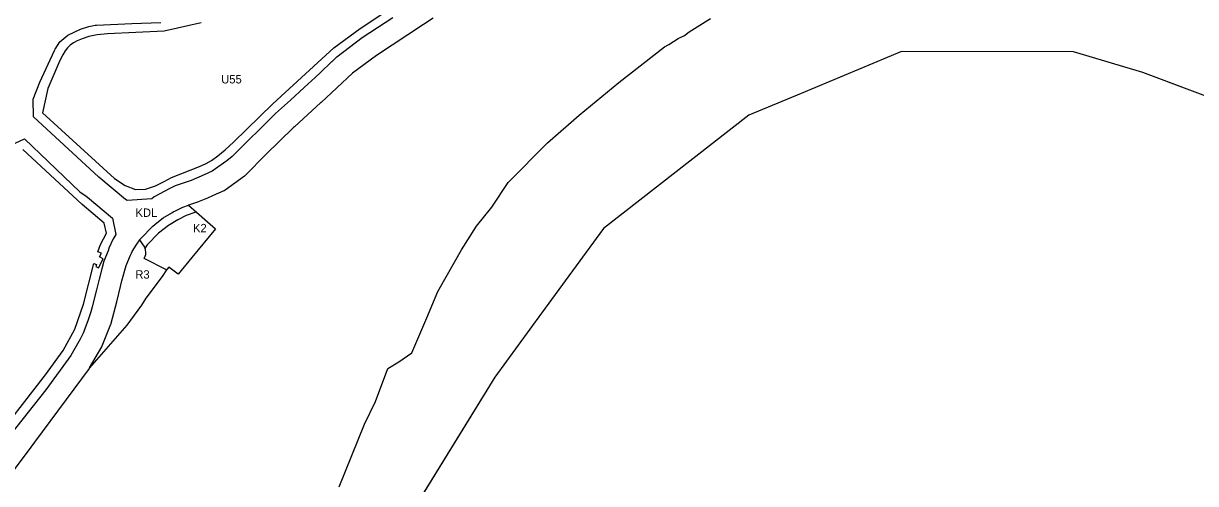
# Model space of a CAD drawing. Extents: x 7428103 to 7431580, y 5545880 to 5549002.
# Drawn here: x 7429439 to 7430217, y 5546339 to 5546645 of the extents above; entities that cross this region are included whole.
import ezdxf

# ---------------------------------------------------------------- set-up
doc = ezdxf.new("R2010")
doc.units = 0
for name, color, linetype in [('CZ_L_granica obszaru objętego planem', 7, 'Continuous'), ('CZ_L_linie rozgraniczające tereny o różnym przeznaczeniu oraz różnych warunkach ich zabudowy i zagospodarowania', 7, 'Continuous'), ('CZ_L_maksymalne nieprzekraczalne linie zabudowy', 7, 'Continuous'), ('CZ_L_opisy_linie rozgraniczające tereny o różnym przeznaczeniu oraz różnych warunkach ich zabudowy i zagospodarowania', 7, 'Continuous')]:
    doc.layers.add(name, color=color, linetype=linetype)

msp = doc.modelspace()

# ---------------------------------------------------------------- linework, layer by layer
at = {"layer": 'CZ_L_granica obszaru objętego planem'}
for p, q in [((7430022.09, 5546625.96), (7429955.41, 5546598.22)), ((7430136.35, 5546625.79), (7430022.09, 5546625.96)), ((7430182.29, 5546612.02), (7430136.35, 5546625.79)), ((7430241.16, 5546589.97), (7430182.29, 5546612.02)), ((7429955.41, 5546598.22), (7429920.79, 5546583.82)), ((7429920.79, 5546583.82), (7429824.25, 5546508.52)), ((7429824.25, 5546508.52), (7429783.16, 5546452.3)), ((7429783.16, 5546452.3), (7429752.12, 5546409.83)), ((7429752.12, 5546409.83), (7429678.23, 5546289.98))]:
    msp.add_line(p, q, dxfattribs=at)
at = {"layer": 'CZ_L_linie rozgraniczające tereny o różnym przeznaczeniu oraz różnych warunkach ich zabudowy i zagospodarowania'}
for p, q in [((7429684.51, 5546648.33), (7429664.19, 5546634.98)), ((7429711.15, 5546647.99), (7429704.83, 5546643.84)), ((7429881.09, 5546639.13), (7429895.22, 5546647.94)), ((7429468.75, 5546636.86), (7429477.04, 5546640.85)), ((7429477.04, 5546640.85), (7429482.63, 5546642.66)), ((7429482.63, 5546642.66), (7429482.65, 5546642.67)), ((7429482.65, 5546642.67), (7429484.85, 5546643.09)), ((7429484.85, 5546643.09), (7429486.9, 5546643.49)), ((7429486.9, 5546643.49), (7429487.78, 5546643.52)), ((7429487.78, 5546643.52), (7429511.19, 5546644.47)), ((7429511.19, 5546644.47), (7429530.49, 5546645.25)), ((7429704.83, 5546643.84), (7429673.62, 5546623.37)), ((7429878.13, 5546636.65), (7429881.09, 5546639.13)), ((7429460.33, 5546627.49), (7429463.44, 5546632.37)), ((7429463.44, 5546632.37), (7429468.75, 5546636.86)), ((7429664.19, 5546634.98), (7429647.18, 5546622.19)), ((7429864.76, 5546629.14), (7429867.67, 5546630.54)), ((7429867.67, 5546630.54), (7429873.82, 5546634.59)), ((7429873.82, 5546634.59), (7429878.13, 5546636.65)), ((7429450.16, 5546605.74), (7429459.9, 5546626.57)), ((7429459.9, 5546626.57), (7429460.33, 5546627.49)), ((7429673.62, 5546623.37), (7429657.76, 5546611.58)), ((7429834.39, 5546605.52), (7429864.76, 5546629.14)), ((7429643.82, 5546619.05), (7429636.42, 5546612.14)), ((7429643.88, 5546619.11), (7429643.82, 5546619.11)), ((7429643.82, 5546619.11), (7429643.82, 5546619.05)), ((7429647.15, 5546622.16), (7429643.88, 5546619.11)), ((7429647.18, 5546622.19), (7429647.15, 5546622.16)), ((7429632.88, 5546608.84), (7429625.65, 5546602.09)), ((7429636.37, 5546612.1), (7429632.88, 5546608.84)), ((7429636.42, 5546612.14), (7429636.37, 5546612.1)), ((7429657.76, 5546611.58), (7429636.78, 5546592.11)), ((7429445.68, 5546594.41), (7429450.16, 5546605.74)), ((7429625.65, 5546602.09), (7429616.47, 5546593.62)), ((7429808.18, 5546583.73), (7429834.39, 5546605.52)), ((7429446.02, 5546582.59), (7429445.68, 5546594.41)), ((7429616.47, 5546593.62), (7429606.57, 5546584.87)), ((7429636.75, 5546592.08), (7429619.18, 5546576.05)), ((7429636.77, 5546592.1), (7429636.75, 5546592.08)), ((7429636.78, 5546592.11), (7429636.77, 5546592.1)), ((7429606.57, 5546584.87), (7429601.7, 5546580.09)), ((7429787.2, 5546565.42), (7429808.18, 5546583.73)), ((7429489.21, 5546542.65), (7429446.02, 5546582.59)), ((7429601.7, 5546580.09), (7429582.94, 5546561.45)), ((7429619.18, 5546576.05), (7429618.62, 5546575.5)), ((7429618.62, 5546575.5), (7429600.18, 5546557.64)), ((7429433.85, 5546565.21), (7429440.07, 5546568.03)), ((7429440.07, 5546568.03), (7429476.81, 5546532.95)), ((7429582.94, 5546561.45), (7429577.71, 5546556.31)), ((7429761.07, 5546538.97), (7429787.2, 5546565.42)), ((7429574.26, 5546553.36), (7429564.63, 5546546.51)), ((7429577.71, 5546556.31), (7429574.26, 5546553.36)), ((7429600.18, 5546557.64), (7429586.75, 5546543.9)), ((7429564.63, 5546546.51), (7429559.22, 5546544.19)), ((7429507.09, 5546527.74), (7429489.21, 5546542.65)), ((7429550.69, 5546540.46), (7429540.07, 5546536.8)), ((7429559.22, 5546544.19), (7429550.69, 5546540.46)), ((7429586.1, 5546543.34), (7429573.24, 5546534.08)), ((7429586.66, 5546543.83), (7429586.1, 5546543.34)), ((7429586.75, 5546543.9), (7429586.66, 5546543.83)), ((7429750.1, 5546522.82), (7429761.07, 5546538.97)), ((7429476.81, 5546532.95), (7429480.93, 5546529.95)), ((7429480.93, 5546529.95), (7429481.73, 5546529.36)), ((7429481.73, 5546529.36), (7429498.43, 5546515.42)), ((7429526.08, 5546529.49), (7429524.44, 5546528.32)), ((7429536.44, 5546535.11), (7429526.08, 5546529.49)), ((7429540.07, 5546536.8), (7429536.44, 5546535.11)), ((7429565.27, 5546530.48), (7429561.4, 5546528.79)), ((7429572.31, 5546533.55), (7429565.27, 5546530.48)), ((7429572.36, 5546533.58), (7429572.31, 5546533.55)), ((7429572.41, 5546533.6), (7429572.36, 5546533.58)), ((7429573.24, 5546534.08), (7429572.41, 5546533.6)), ((7429508.05, 5546527.11), (7429507.09, 5546527.74)), ((7429524.44, 5546528.32), (7429508.05, 5546527.11)), ((7429540.15, 5546520.29), (7429545.12, 5546522.77)), ((7429545.12, 5546522.77), (7429548.78, 5546523.99)), ((7429555.51, 5546526.24), (7429548.78, 5546523.99)), ((7429548.78, 5546523.99), (7429566.77, 5546508.27)), ((7429555.89, 5546526.39), (7429555.51, 5546526.24)), ((7429555.92, 5546526.4), (7429555.89, 5546526.39)), ((7429561.4, 5546528.79), (7429555.92, 5546526.4)), ((7429739.89, 5546510.13), (7429750.1, 5546522.82)), ((7429498.43, 5546515.42), (7429500.59, 5546504.58)), ((7429527.86, 5546512.22), (7429532.08, 5546515.56)), ((7429532.08, 5546515.56), (7429537.75, 5546519)), ((7429537.75, 5546519), (7429538.62, 5546519.53)), ((7429538.62, 5546519.53), (7429540.15, 5546520.29)), ((7429517.4, 5546502.14), (7429525.01, 5546509.94)), ((7429525.01, 5546509.94), (7429525.14, 5546510.07)), ((7429525.14, 5546510.07), (7429527.86, 5546512.22)), ((7429566.77, 5546508.27), (7429551.11, 5546489.35)), ((7429730.02, 5546494.32), (7429739.89, 5546510.13)), ((7429498.73, 5546501.64), (7429495.97, 5546495.43)), ((7429500.59, 5546504.58), (7429498.73, 5546501.64)), ((7429514.08, 5546497.52), (7429516.47, 5546501.14)), ((7429516.47, 5546501.14), (7429516.48, 5546501.17)), ((7429517.89, 5546499.04), (7429516.47, 5546501.14)), ((7429516.48, 5546501.17), (7429516.55, 5546501.27)), ((7429516.55, 5546501.27), (7429517.4, 5546502.14)), ((7429519.78, 5546496.17), (7429517.89, 5546499.04)), ((7429495.49, 5546493.85), (7429492.59, 5546486.84)), ((7429495.93, 5546495.4), (7429495.49, 5546493.85)), ((7429495.97, 5546495.43), (7429495.93, 5546495.41)), ((7429495.93, 5546495.41), (7429495.93, 5546495.4)), ((7429507.54, 5546484.12), (7429510.28, 5546490.78)), ((7429510.28, 5546490.78), (7429510.89, 5546492.27)), ((7429510.89, 5546492.27), (7429511.34, 5546493.36)), ((7429511.34, 5546493.36), (7429514.08, 5546497.52)), ((7429519.72, 5546489.19), (7429520.46, 5546491.37)), ((7429520.25, 5546494.6), (7429519.78, 5546496.17)), ((7429520.48, 5546492.69), (7429520.25, 5546494.6)), ((7429520.46, 5546491.37), (7429520.48, 5546492.69)), ((7429720.71, 5546478.01), (7429730.02, 5546494.32)), ((7429492.59, 5546486.84), (7429491.35, 5546481.81)), ((7429504.63, 5546473.76), (7429507.54, 5546484.12)), ((7429519.44, 5546488.64), (7429519.72, 5546489.19)), ((7429534.31, 5546481.15), (7429519.44, 5546488.64)), ((7429535.79, 5546482.95), (7429534.43, 5546481.34)), ((7429542.04, 5546478.19), (7429535.79, 5546482.95)), ((7429551.11, 5546489.35), (7429542.04, 5546478.19)), ((7429489.47, 5546474.84), (7429487.79, 5546467.91)), ((7429491.35, 5546481.81), (7429489.47, 5546474.84)), ((7429531.27, 5546476.69), (7429520.46, 5546462.33)), ((7429534.31, 5546481.15), (7429531.27, 5546476.69)), ((7429534.43, 5546481.34), (7429534.31, 5546481.15)), ((7429714.3, 5546466.77), (7429720.71, 5546478.01)), ((7429487.79, 5546467.91), (7429484.96, 5546456.55)), ((7429501.24, 5546459.94), (7429503.71, 5546470.01)), ((7429503.71, 5546470.01), (7429504.42, 5546472.89)), ((7429504.42, 5546472.89), (7429504.63, 5546473.76)), ((7429497.57, 5546445.7), (7429501.23, 5546459.88)), ((7429501.23, 5546459.89), (7429501.24, 5546459.94)), ((7429501.23, 5546459.88), (7429501.23, 5546459.89)), ((7429520.46, 5546462.33), (7429517.53, 5546457.71)), ((7429706.92, 5546449.2), (7429714.3, 5546466.77)), ((7429483.81, 5546452.72), (7429482.07, 5546447.27)), ((7429484, 5546453.33), (7429483.81, 5546452.72)), ((7429484.96, 5546456.55), (7429484, 5546453.33)), ((7429517.53, 5546457.71), (7429507.9, 5546444.51)), ((7429482.07, 5546447.27), (7429478.96, 5546439.23)), ((7429507.9, 5546444.51), (7429483.11, 5546416.07)), ((7429491.58, 5546430.8), (7429497.36, 5546445.07)), ((7429497.36, 5546445.07), (7429497.37, 5546445.15)), ((7429497.37, 5546445.15), (7429497.42, 5546445.22)), ((7429497.42, 5546445.22), (7429497.57, 5546445.7)), ((7429697.15, 5546425.97), (7429706.92, 5546449.2)), ((7429478.96, 5546439.23), (7429476.86, 5546435.22)), ((7429476.86, 5546435.22), (7429470.67, 5546424.28)), ((7429483.11, 5546416.07), (7429491.28, 5546430.17)), ((7429491.28, 5546430.17), (7429491.54, 5546430.73)), ((7429491.54, 5546430.73), (7429491.58, 5546430.8)), ((7429470.67, 5546424.28), (7429454.13, 5546401.56)), ((7429688.5, 5546420.12), (7429697.15, 5546425.97)), ((7429482.8, 5546415.61), (7429446.66, 5546366.74)), ((7429482.91, 5546415.79), (7429482.8, 5546415.61)), ((7429483.11, 5546416.07), (7429482.91, 5546415.79)), ((7429673.06, 5546393.84), (7429681.16, 5546415.58)), ((7429681.16, 5546415.58), (7429688.5, 5546420.12)), ((7429454.13, 5546401.56), (7429430.79, 5546371.83)), ((7429665.6, 5546378.66), (7429673.06, 5546393.84)), ((7429648.74, 5546337.15), (7429665.6, 5546378.66)), ((7429446.64, 5546366.72), (7429444.22, 5546363.49)), ((7429446.66, 5546366.74), (7429446.64, 5546366.72)), ((7429446.64, 5546366.72), (7429446.64, 5546366.72)), ((7429444.22, 5546363.49), (7429427.8, 5546341.59))]:
    msp.add_line(p, q, dxfattribs=at)
msp.add_lwpolyline([(7430241.16, 5546589.97), (7430182.29, 5546612.02), (7430136.35, 5546625.79), (7430022.09, 5546625.96), (7429955.41, 5546598.22), (7429920.79, 5546583.82), (7429824.25, 5546508.52), (7429783.16, 5546452.3), (7429752.12, 5546409.83), (7429678.23, 5546289.98), (7429652.81, 5546204.83), (7429649.63, 5546196.69), (7429632.73, 5546153.44), (7429595.88, 5546064.11), (7429579.31, 5546032.44), (7429578.15, 5546030.38), (7429558.63, 5545995.53), (7429542.28, 5545977.17), (7429513.3, 5545949.5), (7429501.33, 5545940.48), (7429462.98, 5545911.59), (7429428.5, 5545898.86)], dxfattribs=at)
at = {"layer": 'CZ_L_maksymalne nieprzekraczalne linie zabudowy'}
for points in [[(7429520.26, 5546534.62), (7429526.83, 5546536.81), (7429532.72, 5546539.65), (7429537.65, 5546542.29), (7429556.24, 5546549.61), (7429560.53, 5546551.6), (7429564.16, 5546553.77), (7429568.4, 5546556.82), (7429573.24, 5546560.81), (7429578.73, 5546565.88), (7429604.87, 5546591.37), (7429637.33, 5546621.2), (7429645.36, 5546628.3), (7429662.79, 5546641.23), (7429707.96, 5546671.22)], [(7429557.18, 5546644.99), (7429532.57, 5546639.47), (7429494.97, 5546637.73), (7429488.25, 5546637.02), (7429482.59, 5546635.83), (7429478.21, 5546634.45), (7429474.92, 5546633.1), (7429472.4, 5546631.73), (7429470.27, 5546630.2), (7429468.45, 5546628.44), (7429466.87, 5546626.35), (7429465.31, 5546623.67), (7429463.45, 5546619.9), (7429455.46, 5546601.35), (7429451.94, 5546585.29), (7429499.71, 5546541.79), (7429506.71, 5546537), (7429513.72, 5546534.39), (7429520.26, 5546534.62)], [(7429416.4, 5546363.22), (7429453.91, 5546411.45), (7429465.6, 5546427.52), (7429473.46, 5546441.69), (7429479.21, 5546458.27), (7429486.03, 5546485.32), (7429487.66, 5546484.71), (7429487.26, 5546483.34), (7429489.06, 5546482.38), (7429492.19, 5546488.5), (7429489.84, 5546489.76), (7429491, 5546492.2), (7429488.58, 5546493.07), (7429490.45, 5546497.84), (7429494.3, 5546505.45), (7429492.96, 5546512.17), (7429478.18, 5546524.51), (7429438.86, 5546560.89)], [(7429553.79, 5546519.34), (7429547.25, 5546517.13), (7429541.69, 5546514.35), (7429535.51, 5546510.62), (7429528.94, 5546505.37), (7429521.47, 5546497.72), (7429519.62, 5546495.02)]]:
    msp.add_lwpolyline(points, dxfattribs=at)

# ---------------------------------------------------------------- texts
at = {"layer": 'CZ_L_opisy_linie rozgraniczające tereny o różnym przeznaczeniu oraz różnych warunkach ich zabudowy i zagospodarowania'}
for s, p in [('U55', (7429570.55, 5546604.79)), ('KDL', (7429513.64, 5546516.29)), ('K2', (7429551.84, 5546506.06)), ('R3', (7429513.57, 5546475.31))]:
    msp.add_text(s, height=5.549, dxfattribs=at).set_placement(p)

doc.saveas('drawing.dxf')
